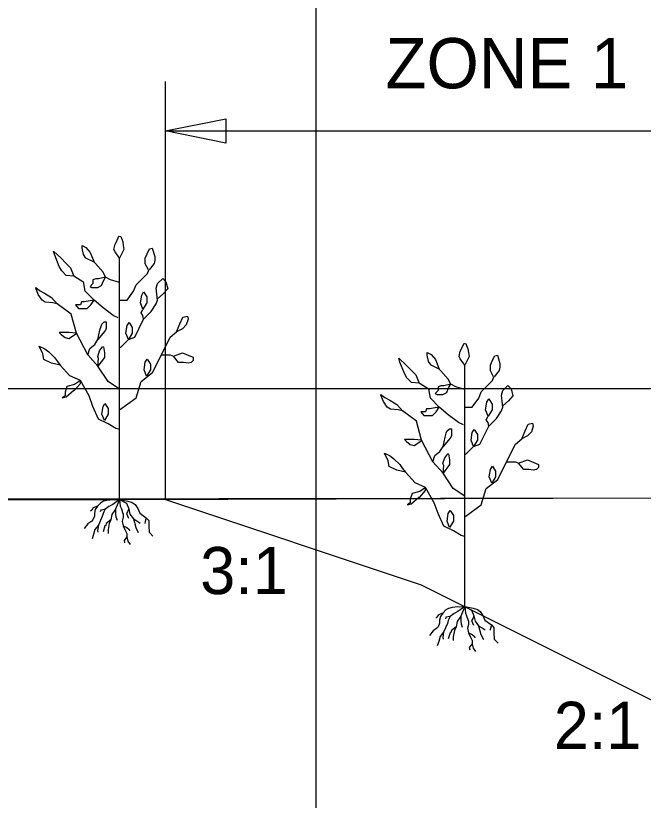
# Model space of a CAD drawing. Extents: x 1578769 to 1579225, y 724002 to 724828.
# Drawn here: x 1578851.21 to 1578857.45, y 724319.06 to 724326.86 of the extents above; entities that cross this region are included whole.
import ezdxf

# ---------------------------------------------------------------- set-up
doc = ezdxf.new("R2010")
doc.units = 0
for name, color, linetype in [('1', 7, 'Continuous'), ('Default', 7, 'Continuous'), ('Old_Level_41', 7, 'Continuous'), ('R_Exist Surface', 7, 'Continuous'), ('R_Fin Surface', 7, 'Continuous')]:
    doc.layers.add(name, color=color, linetype=linetype)

msp = doc.modelspace()

# ---------------------------------------------------------------- linework, layer by layer
at = {"layer": '1'}
for p, q in [((1578852.6996, 724322.0475), (1578852.6996, 724326.2055)), ((1578852.6996, 724325.7134), (1578859.4051, 724325.7134)), ((1578852.2427, 724322.0476), (1578852.2427, 724324.4475)), ((1578855.6753, 724320.9833), (1578855.6753, 724323.3833)), ((1578852.2473, 724322.0425), (1578852.2491, 724322.0466)), ((1578855.68, 724320.9783), (1578855.6818, 724320.9823))]:
    msp.add_line(p, q, dxfattribs=at)
for points in [[(1578853.2996, 724325.5934), (1578852.6996, 724325.7134), (1578853.2996, 724325.8334)], [(1578852.2427, 724324.4475), (1578852.1985, 724324.5107), (1578852.1859, 724324.536), (1578852.1985, 724324.5865), (1578852.2112, 724324.6117), (1578852.2364, 724324.6686), (1578852.2553, 724324.6623), (1578852.2743, 724324.6117), (1578852.2806, 724324.5738), (1578852.2869, 724324.536)], [(1578851.7883, 724324.2707), (1578851.7126, 724324.277), (1578851.6684, 724324.3212), (1578851.6432, 724324.3654), (1578851.599, 724324.4791), (1578851.5864, 724324.517), (1578851.6621, 724324.4475), (1578851.7063, 724324.4033), (1578851.7568, 724324.3528)], [(1578851.9902, 724324.4096), (1578851.9082, 724324.4475), (1578851.883, 724324.4854), (1578851.8704, 724324.5486), (1578851.8704, 724324.5739), (1578851.9082, 724324.5549), (1578851.9524, 724324.5044)], [(1578852.1038, 724324.258), (1578852.0353, 724324.2434), (1578852.0066, 724324.2434), (1578851.978, 724324.2338), (1578851.978, 724324.1956), (1578851.9493, 724324.167), (1578851.9684, 724324.1574), (1578852.0257, 724324.1574), (1578852.0639, 724324.1765), (1578852.083, 724324.2243)], [(1578851.9902, 724324.0307), (1578851.9493, 724324.0237), (1578851.8921, 724324.0141), (1578851.8634, 724324.0141), (1578851.8539, 724323.9855), (1578851.8061, 724323.9855), (1578851.8348, 724323.9472), (1578851.873, 724323.9472), (1578851.9207, 724323.9472), (1578851.9589, 724323.9855)], [(1578852.0281, 724323.6391), (1578852.047, 724323.7338), (1578852.0597, 724323.7717), (1578852.066, 724323.7907), (1578852.0912, 724323.8159), (1578852.1102, 724323.8159), (1578852.1102, 724323.7465), (1578852.0975, 724323.7212)], [(1578851.6534, 724323.3836), (1578851.5675, 724323.4027), (1578851.4911, 724323.4409), (1578851.4816, 724323.4982), (1578851.4434, 724323.5747), (1578851.5007, 724323.546), (1578851.5389, 724323.5173), (1578851.5961, 724323.46), (1578851.6248, 724323.4218)], [(1578855.6753, 724323.3833), (1578855.6312, 724323.4464), (1578855.6186, 724323.4717), (1578855.6312, 724323.5222), (1578855.6438, 724323.5475), (1578855.6691, 724323.6043), (1578855.688, 724323.598), (1578855.707, 724323.5475), (1578855.7133, 724323.5096), (1578855.7196, 724323.4717)], [(1578852.0281, 724323.3739), (1578852.0353, 724323.4505), (1578852.0257, 724323.4696), (1578852.0448, 724323.5269), (1578852.0735, 724323.5651), (1578852.083, 724323.5651), (1578852.0925, 724323.5078), (1578852.0925, 724323.46)], [(1578855.4229, 724323.3454), (1578855.3409, 724323.3833), (1578855.3157, 724323.4212), (1578855.303, 724323.4843), (1578855.303, 724323.5096), (1578855.3409, 724323.4907), (1578855.3851, 724323.4401)], [(1578855.2209, 724323.2064), (1578855.1453, 724323.2127), (1578855.1011, 724323.257), (1578855.0758, 724323.3012), (1578855.0317, 724323.4148), (1578855.019, 724323.4527), (1578855.0948, 724323.3833), (1578855.1389, 724323.3391), (1578855.1894, 724323.2885)], [(1578851.8539, 724323.2307), (1578851.7966, 724323.1925), (1578851.7202, 724323.1734), (1578851.7011, 724323.1161), (1578851.7011, 724323.0779), (1578851.6725, 724323.0588), (1578851.7107, 724323.0683), (1578851.7871, 724323.1352), (1578851.7966, 724323.1352), (1578851.8539, 724323.2021)], [(1578855.5365, 724323.1938), (1578855.4679, 724323.1791), (1578855.4393, 724323.1791), (1578855.4107, 724323.1696), (1578855.4107, 724323.1314), (1578855.382, 724323.1027), (1578855.4011, 724323.0932), (1578855.4584, 724323.0932), (1578855.4966, 724323.1123), (1578855.5157, 724323.16)], [(1578855.4229, 724322.9664), (1578855.382, 724322.9594), (1578855.3247, 724322.9499), (1578855.2961, 724322.9499), (1578855.2866, 724322.9212), (1578855.2388, 724322.9212), (1578855.2675, 724322.883), (1578855.3056, 724322.883), (1578855.3534, 724322.883), (1578855.3916, 724322.9212)], [(1578855.4608, 724322.5749), (1578855.4797, 724322.6696), (1578855.4923, 724322.7075), (1578855.4987, 724322.7264), (1578855.5239, 724322.7517), (1578855.5428, 724322.7517), (1578855.5428, 724322.6822), (1578855.5302, 724322.657)], [(1578855.0861, 724322.3193), (1578855.0002, 724322.3384), (1578854.9238, 724322.3767), (1578854.9142, 724322.434), (1578854.8761, 724322.5104), (1578854.9333, 724322.4817), (1578854.9715, 724322.4531), (1578855.0288, 724322.3958), (1578855.0574, 724322.3576)], [(1578855.4608, 724322.3096), (1578855.4679, 724322.3862), (1578855.4584, 724322.4053), (1578855.4775, 724322.4626), (1578855.5061, 724322.5009), (1578855.5157, 724322.5009), (1578855.5252, 724322.4435), (1578855.5252, 724322.3958)], [(1578855.2866, 724322.1665), (1578855.2293, 724322.1283), (1578855.1529, 724322.1092), (1578855.1338, 724322.0518), (1578855.1338, 724322.0136), (1578855.1052, 724321.9945), (1578855.1434, 724322.0041), (1578855.2197, 724322.0709), (1578855.2293, 724322.0709), (1578855.2866, 724322.1378)]]:
    msp.add_lwpolyline(points, close=True, dxfattribs=at)
for points in [[(1578852.5298, 724324.3338), (1578852.4983, 724324.3907), (1578852.4983, 724324.4475), (1578852.5172, 724324.4917), (1578852.5425, 724324.5423), (1578852.5677, 724324.5486), (1578852.593, 724324.4665), (1578852.593, 724324.4286), (1578852.5866, 724324.397), (1578852.5362, 724324.3338)], [(1578852.2427, 724324.2075), (1578852.1543, 724324.2328), (1578852.1038, 724324.258), (1578852.0786, 724324.3086), (1578852.0029, 724324.397), (1578851.9902, 724324.4096)], [(1578852.2301, 724323.8538), (1578852.1796, 724323.8791), (1578852.0786, 724323.9549), (1578851.9902, 724324.0307), (1578851.9019, 724324.1191), (1578851.8893, 724324.1949), (1578851.8893, 724324.2075), (1578851.7883, 724324.2707)], [(1578852.2427, 724324.0307), (1578852.3184, 724324.0307), (1578852.3815, 724324.1191), (1578852.4068, 724324.1823), (1578852.5204, 724324.2959), (1578852.533, 724324.3338)], [(1578852.6213, 724324.0307), (1578852.6088, 724324.1507), (1578852.6214, 724324.1949), (1578852.6719, 724324.2454), (1578852.7034, 724324.2138), (1578852.7224, 724324.1444), (1578852.6782, 724324.0939), (1578852.6214, 724324.0433)], [(1578851.6242, 724323.9928), (1578851.5801, 724324.0054), (1578851.5043, 724324.0118), (1578851.4728, 724324.0307), (1578851.4349, 724324.0875), (1578851.4097, 724324.1507), (1578851.4097, 724324.157), (1578851.4475, 724324.1254), (1578851.498, 724324.1002), (1578851.5674, 724324.056), (1578851.6242, 724323.9928)], [(1578852.4762, 724323.9423), (1578852.451, 724324.0054), (1578852.4636, 724324.0812), (1578852.4825, 724324.1128), (1578852.5141, 724324.0623), (1578852.5141, 724324.0054), (1578852.4762, 724323.9423)], [(1578852.2427, 724323.1465), (1578852.1291, 724323.2223), (1578852.0281, 724323.3739), (1578851.9271, 724323.4875), (1578851.8135, 724323.7023), (1578851.763, 724323.8917), (1578851.6242, 724323.9928)], [(1578852.2427, 724323.5633), (1578852.2553, 724323.5633), (1578852.331, 724323.6391), (1578852.3941, 724323.6644), (1578852.4825, 724323.8412), (1578852.5582, 724323.917), (1578852.6087, 724323.9928), (1578852.6213, 724324.0307)], [(1578852.4825, 724323.8412), (1578852.4762, 724323.8791), (1578852.4573, 724323.9044), (1578852.4762, 724323.9423)], [(1578852.331, 724323.6391), (1578852.3058, 724323.7023), (1578852.3184, 724323.7781), (1578852.3373, 724323.8096), (1578852.3689, 724323.7591), (1578852.3689, 724323.7023), (1578852.331, 724323.6391)], [(1578852.8107, 724323.7149), (1578852.8423, 724323.797), (1578852.8738, 724323.8602), (1578852.918, 724323.8728), (1578852.9243, 724323.8412), (1578852.9054, 724323.7844), (1578852.8675, 724323.7465), (1578852.8107, 724323.7149)], [(1578851.8135, 724323.7023), (1578851.7393, 724323.7084), (1578851.682, 724323.7084), (1578851.6439, 724323.7084), (1578851.6629, 724323.6893), (1578851.7011, 724323.6606), (1578851.7393, 724323.6511), (1578851.8157, 724323.6989)], [(1578852.2427, 724322.9386), (1578852.4068, 724323.0581), (1578852.4573, 724323.2223), (1578852.5709, 724323.3107), (1578852.6592, 724323.4875), (1578852.7476, 724323.6644), (1578852.8107, 724323.7149)], [(1578851.9271, 724323.4875), (1578851.9461, 724323.5507), (1578851.9966, 724323.5886), (1578852.0281, 724323.6391)], [(1578852.7791, 724323.4749), (1578852.8675, 724323.5065), (1578852.9306, 724323.4812), (1578852.9748, 724323.4623), (1578852.9748, 724323.4307), (1578852.9559, 724323.4117), (1578852.9243, 724323.4054), (1578852.8801, 724323.4117), (1578852.8296, 724323.4117), (1578852.7791, 724323.4749)], [(1578852.512, 724323.2735), (1578852.4868, 724323.3367), (1578852.4994, 724323.4125), (1578852.5183, 724323.444), (1578852.5499, 724323.3935), (1578852.5499, 724323.3367), (1578852.512, 724323.2735)], [(1578852.6592, 724323.4875), (1578852.7223, 724323.4875), (1578852.7476, 724323.4875), (1578852.7791, 724323.4749)], [(1578855.9625, 724323.2696), (1578855.931, 724323.3264), (1578855.931, 724323.3833), (1578855.9499, 724323.4275), (1578855.9751, 724323.478), (1578856.0004, 724323.4843), (1578856.0256, 724323.4022), (1578856.0256, 724323.3643), (1578856.0193, 724323.3328), (1578855.9688, 724323.2696)], [(1578852.2453, 724322.7435), (1578852.2071, 724322.7531), (1578852.1307, 724322.8008), (1578852.0353, 724322.8486), (1578851.978, 724322.9728), (1578851.9398, 724323.0779), (1578851.8539, 724323.2307), (1578851.7489, 724323.2785), (1578851.6534, 724323.3836), (1578851.6534, 724323.3836)], [(1578855.6754, 724323.1433), (1578855.587, 724323.1685), (1578855.5365, 724323.1938), (1578855.5113, 724323.2443), (1578855.4355, 724323.3327), (1578855.4229, 724323.3454)], [(1578855.6754, 724322.9664), (1578855.7511, 724322.9664), (1578855.8142, 724323.0548), (1578855.8394, 724323.118), (1578855.953, 724323.2317), (1578855.9657, 724323.2696)], [(1578855.6627, 724322.7896), (1578855.6122, 724322.8149), (1578855.5113, 724322.8906), (1578855.4229, 724322.9664), (1578855.3345, 724323.0548), (1578855.3219, 724323.1306), (1578855.3219, 724323.1433), (1578855.2209, 724323.2064)], [(1578856.054, 724322.9664), (1578856.0414, 724323.0864), (1578856.0541, 724323.1307), (1578856.1045, 724323.1812), (1578856.1361, 724323.1496), (1578856.155, 724323.0801), (1578856.1109, 724323.0296), (1578856.0541, 724322.9791)], [(1578855.0569, 724322.9285), (1578855.0127, 724322.9412), (1578854.937, 724322.9475), (1578854.9054, 724322.9665), (1578854.8676, 724323.0233), (1578854.8423, 724323.0864), (1578854.8423, 724323.0928), (1578854.8802, 724323.0612), (1578854.9307, 724323.0359), (1578855.0001, 724322.9917), (1578855.0569, 724322.9285)], [(1578855.9089, 724322.878), (1578855.8836, 724322.9412), (1578855.8963, 724323.017), (1578855.9152, 724323.0485), (1578855.9468, 724322.998), (1578855.9468, 724322.9412), (1578855.9089, 724322.878)], [(1578852.092, 724322.8341), (1578852.0667, 724322.8972), (1578852.0793, 724322.973), (1578852.0983, 724323.0046), (1578852.1298, 724322.9541), (1578852.1298, 724322.8972), (1578852.092, 724322.8341)], [(1578855.6754, 724322.4991), (1578855.688, 724322.4991), (1578855.7637, 724322.5749), (1578855.8268, 724322.6001), (1578855.9152, 724322.777), (1578855.9909, 724322.8527), (1578856.0414, 724322.9285), (1578856.054, 724322.9664)], [(1578855.6754, 724322.0822), (1578855.5618, 724322.158), (1578855.4608, 724322.3096), (1578855.3598, 724322.4233), (1578855.2462, 724322.638), (1578855.1957, 724322.8275), (1578855.0569, 724322.9285)], [(1578855.9152, 724322.777), (1578855.9089, 724322.8149), (1578855.8899, 724322.8401), (1578855.9089, 724322.878)], [(1578856.2434, 724322.6506), (1578856.275, 724322.7328), (1578856.3065, 724322.7959), (1578856.3507, 724322.8085), (1578856.357, 724322.777), (1578856.3381, 724322.7201), (1578856.3002, 724322.6822), (1578856.2434, 724322.6506)], [(1578855.7637, 724322.5749), (1578855.7385, 724322.638), (1578855.7511, 724322.7138), (1578855.77, 724322.7454), (1578855.8016, 724322.6949), (1578855.8016, 724322.638), (1578855.7637, 724322.5749)], [(1578855.2462, 724322.638), (1578855.172, 724322.6442), (1578855.1147, 724322.6442), (1578855.0765, 724322.6442), (1578855.0956, 724322.6251), (1578855.1338, 724322.5964), (1578855.172, 724322.5868), (1578855.2484, 724322.6346)], [(1578855.6753, 724321.8744), (1578855.8394, 724321.9938), (1578855.8899, 724322.158), (1578856.0035, 724322.2464), (1578856.0919, 724322.4233), (1578856.1802, 724322.6001), (1578856.2434, 724322.6506)], [(1578855.3598, 724322.4233), (1578855.3788, 724322.4865), (1578855.4292, 724322.5243), (1578855.4608, 724322.5749)], [(1578856.0919, 724322.4233), (1578856.155, 724322.4233), (1578856.1803, 724322.4233), (1578856.2118, 724322.4107)], [(1578856.2118, 724322.4107), (1578856.3002, 724322.4422), (1578856.3633, 724322.417), (1578856.4075, 724322.398), (1578856.4075, 724322.3664), (1578856.3885, 724322.3475), (1578856.357, 724322.3412), (1578856.3128, 724322.3475), (1578856.2623, 724322.3475), (1578856.2118, 724322.4107)], [(1578855.678, 724321.6793), (1578855.6398, 724321.6888), (1578855.5634, 724321.7366), (1578855.468, 724321.7843), (1578855.4107, 724321.9085), (1578855.3725, 724322.0136), (1578855.2866, 724322.1665), (1578855.1816, 724322.2143), (1578855.0861, 724322.3193), (1578855.0861, 724322.3193)], [(1578855.9447, 724322.2093), (1578855.9194, 724322.2724), (1578855.9321, 724322.3482), (1578855.951, 724322.3798), (1578855.9826, 724322.3293), (1578855.9826, 724322.2724), (1578855.9447, 724322.2093)], [(1578852.2427, 724322.0476), (1578852.1913, 724322.0418), (1578852.1757, 724322.0456), (1578852.1176, 724322.0379), (1578852.0826, 724322.0301), (1578852.0555, 724322.0146), (1578852.0245, 724321.9835), (1578852.0012, 724321.9486), (1578851.9934, 724321.9136), (1578851.9934, 724321.8826), (1578851.9779, 724321.8476), (1578851.9662, 724321.8321), (1578851.9274, 724321.8049), (1578851.8925, 724321.7583)], [(1578852.2427, 724322.0476), (1578852.1757, 724321.999), (1578852.137, 724321.9796), (1578852.0982, 724321.9486), (1578852.0788, 724321.9098), (1578852.071, 724321.8787), (1578852.0322, 724321.7933), (1578851.9973, 724321.7506), (1578851.9857, 724321.7001), (1578851.9701, 724321.6574)], [(1578852.2427, 724322.0476), (1578852.2029, 724321.9524), (1578852.168, 724321.8981), (1578852.1563, 724321.8476), (1578852.1408, 724321.8088), (1578852.1292, 724321.7506), (1578852.1292, 724321.7117)], [(1578852.2427, 724322.0476), (1578852.3266, 724322.0315), (1578852.3697, 724322.0185), (1578852.3969, 724321.999), (1578852.424, 724321.9602), (1578852.4434, 724321.9136), (1578852.5094, 724321.8671), (1578852.5327, 724321.8399), (1578852.5327, 724321.7816), (1578852.5366, 724321.7234), (1578852.5753, 724321.6846)], [(1578852.2427, 724322.0476), (1578852.3115, 724322.0107), (1578852.3348, 724321.9563), (1578852.3464, 724321.902), (1578852.3814, 724321.8554), (1578852.4047, 724321.77), (1578852.4279, 724321.7195)], [(1578852.2427, 724322.0476), (1578852.2495, 724321.9835), (1578852.2611, 724321.9563), (1578852.2727, 724321.9175), (1578852.2805, 724321.902), (1578852.2805, 724321.8709), (1578852.2689, 724321.8321), (1578852.2805, 724321.7855), (1578852.296, 724321.7506), (1578852.3154, 724321.7117), (1578852.3154, 724321.6768), (1578852.327, 724321.6341), (1578852.3503, 724321.5992)], [(1578852.0245, 724321.9835), (1578851.9818, 724321.9641), (1578851.9662, 724321.9408), (1578851.9546, 724321.933)], [(1578852.0982, 724321.9486), (1578852.0555, 724321.9408), (1578852.0516, 724321.9253)], [(1578852.2029, 724321.9524), (1578852.2029, 724321.8981), (1578852.2068, 724321.8748), (1578852.2184, 724321.8437)], [(1578852.3348, 724321.9563), (1578852.3232, 724321.9253), (1578852.3115, 724321.9098), (1578852.3309, 724321.8632)], [(1578855.5246, 724321.7698), (1578855.4994, 724321.833), (1578855.512, 724321.9088), (1578855.5309, 724321.9403), (1578855.5625, 724321.8898), (1578855.5625, 724321.833), (1578855.5246, 724321.7698)], [(1578852.3814, 724321.8554), (1578852.4163, 724321.836), (1578852.4357, 724321.8243), (1578852.4473, 724321.8127)], [(1578852.5094, 724321.8671), (1578852.4978, 724321.8282), (1578852.4939, 724321.8088)], [(1578852.0322, 724321.7933), (1578852.0245, 724321.7389), (1578852.0283, 724321.7234)], [(1578852.1563, 724321.8476), (1578852.1098, 724321.8088), (1578852.1059, 724321.7894), (1578852.0982, 724321.7855), (1578852.0788, 724321.7273)], [(1578852.2805, 724321.7855), (1578852.3154, 724321.77), (1578852.3387, 724321.7506), (1578852.3426, 724321.7351)], [(1578852.3154, 724321.6768), (1578852.2883, 724321.6419), (1578852.2922, 724321.6186)], [(1578855.6753, 724320.9833), (1578855.6239, 724320.9775), (1578855.6084, 724320.9814), (1578855.5502, 724320.9736), (1578855.5153, 724320.9658), (1578855.4882, 724320.9503), (1578855.4571, 724320.9193), (1578855.4338, 724320.8843), (1578855.4261, 724320.8494), (1578855.4261, 724320.8183), (1578855.4106, 724320.7834), (1578855.3989, 724320.7678), (1578855.3601, 724320.7407), (1578855.3252, 724320.6941)], [(1578855.4571, 724320.9193), (1578855.4144, 724320.8999), (1578855.3989, 724320.8766), (1578855.3873, 724320.8688)], [(1578855.6753, 724320.9833), (1578855.6084, 724320.9348), (1578855.5696, 724320.9154), (1578855.5308, 724320.8843), (1578855.5114, 724320.8455), (1578855.5037, 724320.8144), (1578855.4649, 724320.729), (1578855.43, 724320.6863), (1578855.4183, 724320.6358), (1578855.4028, 724320.5931)], [(1578855.6753, 724320.9833), (1578855.6356, 724320.8882), (1578855.6007, 724320.8339), (1578855.589, 724320.7834), (1578855.5735, 724320.7446), (1578855.5619, 724320.6863), (1578855.5619, 724320.6475)], [(1578855.6753, 724320.9833), (1578855.7593, 724320.9672), (1578855.8024, 724320.9542), (1578855.8296, 724320.9348), (1578855.8567, 724320.896), (1578855.8761, 724320.8494), (1578855.9421, 724320.8028), (1578855.9654, 724320.7756), (1578855.9654, 724320.7174), (1578855.9692, 724320.6591), (1578856.008, 724320.6203)], [(1578855.6753, 724320.9833), (1578855.7442, 724320.9464), (1578855.7675, 724320.8921), (1578855.7791, 724320.8377), (1578855.814, 724320.7911), (1578855.8373, 724320.7057), (1578855.8606, 724320.6552)], [(1578855.6753, 724320.9833), (1578855.6821, 724320.9193), (1578855.6938, 724320.8921), (1578855.7054, 724320.8533), (1578855.7132, 724320.8377), (1578855.7132, 724320.8067), (1578855.7015, 724320.7678), (1578855.7132, 724320.7213), (1578855.7287, 724320.6863), (1578855.7481, 724320.6475), (1578855.7481, 724320.6126), (1578855.7597, 724320.5699), (1578855.783, 724320.5349)], [(1578855.5308, 724320.8843), (1578855.4882, 724320.8766), (1578855.4843, 724320.861)], [(1578855.6356, 724320.8882), (1578855.6356, 724320.8339), (1578855.6394, 724320.8106), (1578855.6511, 724320.7795)], [(1578855.7675, 724320.8921), (1578855.7559, 724320.861), (1578855.7442, 724320.8455), (1578855.7636, 724320.7989)], [(1578855.589, 724320.7834), (1578855.5425, 724320.7446), (1578855.5386, 724320.7252), (1578855.5308, 724320.7213), (1578855.5114, 724320.663)], [(1578855.814, 724320.7911), (1578855.849, 724320.7717), (1578855.8684, 724320.7601), (1578855.88, 724320.7485)], [(1578855.9421, 724320.8028), (1578855.9304, 724320.764), (1578855.9265, 724320.7446)], [(1578855.4649, 724320.729), (1578855.4571, 724320.6747), (1578855.461, 724320.6591)], [(1578855.7132, 724320.7213), (1578855.7481, 724320.7057), (1578855.7714, 724320.6863), (1578855.7752, 724320.6708)], [(1578855.7481, 724320.6126), (1578855.7209, 724320.5776), (1578855.7248, 724320.5543)]]:
    msp.add_lwpolyline(points, dxfattribs=at)
at = {"layer": 'Default'}
msp.add_lwpolyline([(1578822.9439, 724322.1501), (1578824.3539, 724322.1046), (1578827.2539, 724322.0875), (1578831.4239, 724322.0631), (1578836.8239, 724322.0314), (1578858.5939, 724322.0681), (1578861.1339, 724322.0669), (1578862.9439, 724322.0712), (1578882.4539, 724322.0121), (1578884.5239, 724320.4129), (1578890.3939, 724312.7963), (1578905.4439, 724309.3885), (1578918.1239, 724306.8519), (1578923.7639, 724306.9982), (1578939.0039, 724307.3934), (1578947.2439, 724307.6071), (1578961.8739, 724307.8524), (1578966.5939, 724307.868), (1579023.7239, 724312.4122), (1579059.0839, 724315.3747), (1579126.2439, 724320.0384), (1579145.7939, 724321.276)], dxfattribs=at)
at = {"layer": 'Old_Level_41'}
msp.add_line((1578854.1939, 724333.1501), (1578854.1939, 724303.1501), dxfattribs=at)
msp.add_lwpolyline([(1578924.1939, 724323.1501), (1578824.1939, 724323.1501)], dxfattribs=at)
at = {"layer": 'R_Exist Surface'}
msp.add_lwpolyline([(1578824.1939, 724322.1622), (1578829.284, 724322.0912), (1578836.2755, 724322.0556), (1578841.2426, 724322.0491), (1578852.2427, 724322.0476), (1578866.2522, 724322.0925), (1578877.2091, 724322.0144), (1578882.2159, 724322.036), (1578883.2289, 724321.4278), (1578884.2158, 724320.6364), (1578885.2591, 724319.5036), (1578887.3767, 724316.6913), (1578890.5015, 724312.7881), (1578895.2522, 724311.6936), (1578904.139, 724309.6792), (1578908.2007, 724308.813), (1578914.4913, 724307.5769), (1578918.1855, 724306.8444), (1578924.1939, 724307.0119)], dxfattribs=at)
at = {"layer": 'R_Fin Surface'}
for p, q in [((1578852.6996, 724322.0475), (1578855.2417, 724321.2002)), ((1578852.6996, 724322.0475), (1578855.2417, 724321.2002)), ((1578855.2417, 724321.2002), (1578859.4051, 724319.1184)), ((1578855.2417, 724321.2002), (1578859.4051, 724319.1184))]:
    msp.add_line(p, q, dxfattribs=at)

# ---------------------------------------------------------------- texts
at = {"layer": '1'}
for s, height, p in [('ZONE 1', 0.5, (1578854.8874, 724326.1375)), ('3:1', 0.46875, (1578853.0452, 724321.1072)), ('2:1', 0.46875, (1578856.561, 724319.5682))]:
    msp.add_text(s, height=height, dxfattribs=at).set_placement(p)

doc.saveas('drawing.dxf')
